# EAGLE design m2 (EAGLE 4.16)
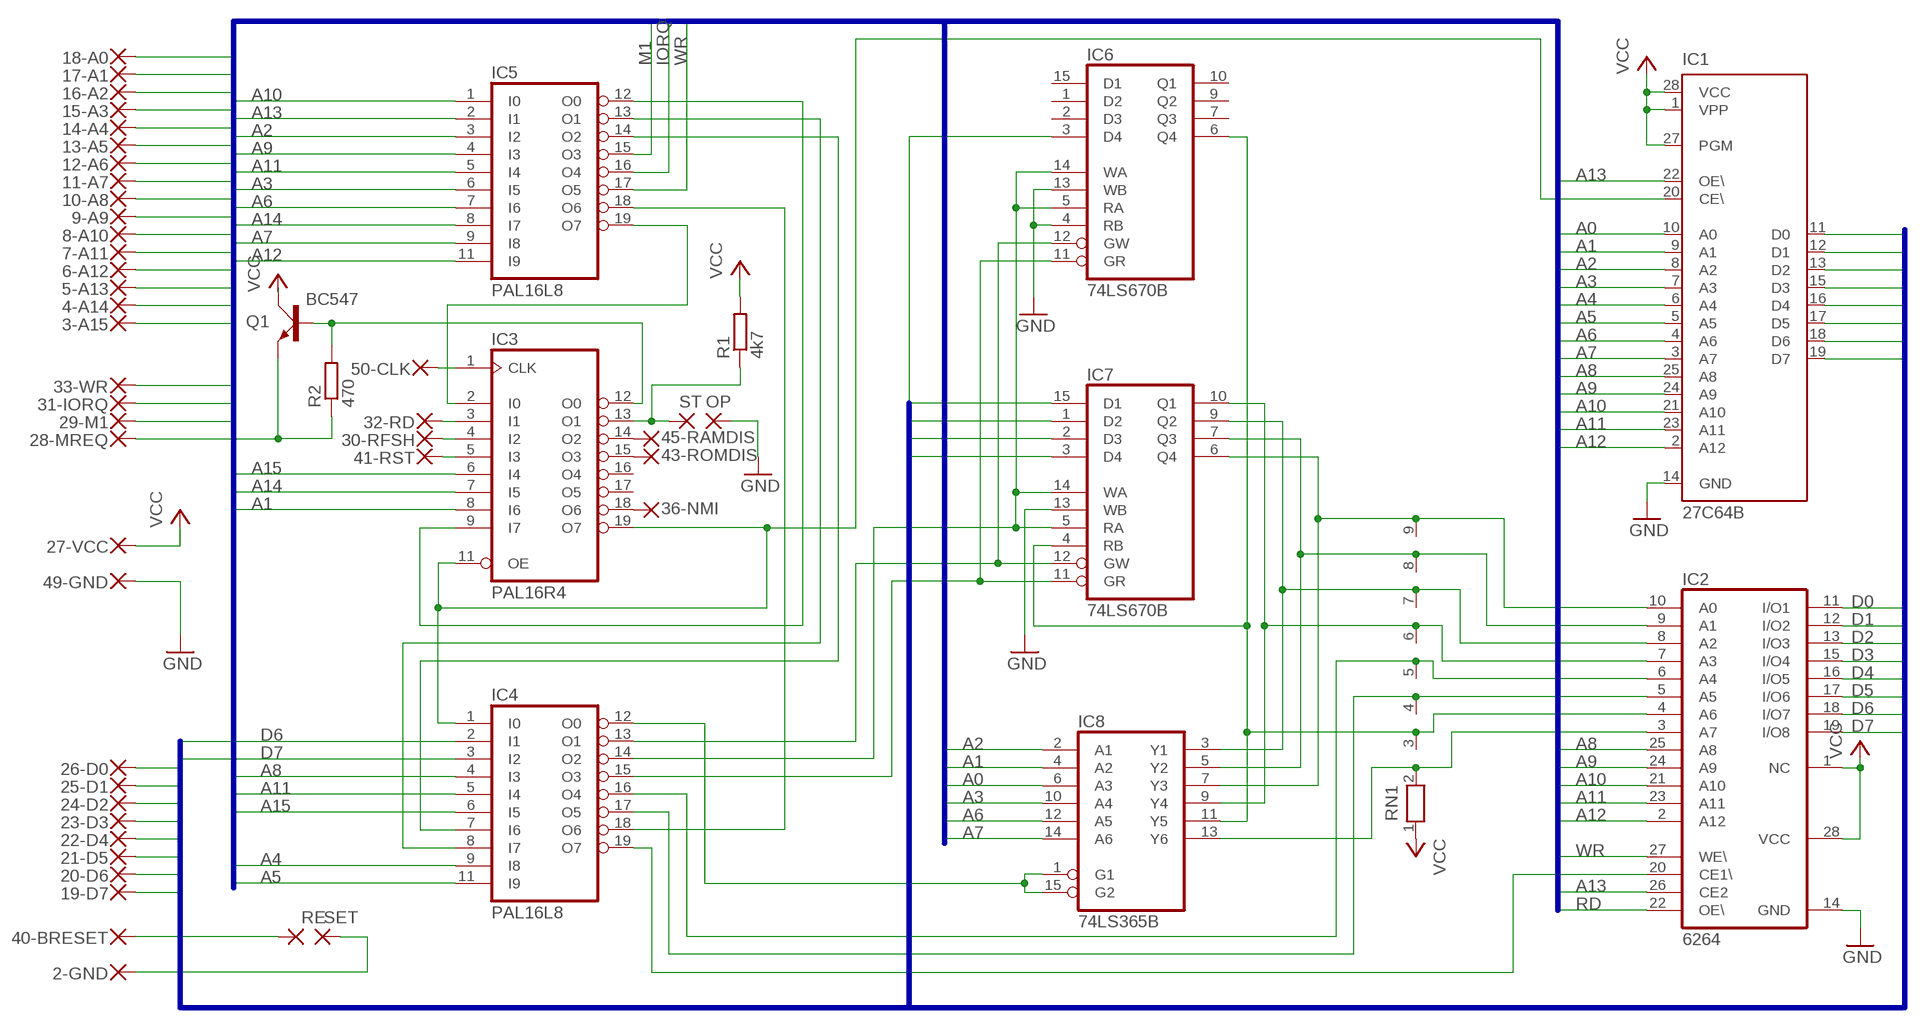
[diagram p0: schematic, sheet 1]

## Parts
2-GND  1,27-REDONDO0.8  [1,27/0,8-REDONDO]
3-A15  1,27-REDONDO0.8  [1,27/0,8-REDONDO]
4-A14  1,27-REDONDO0.8  [1,27/0,8-REDONDO]
5-A13  1,27-REDONDO0.8  [1,27/0,8-REDONDO]
6-A12  1,27-REDONDO0.8  [1,27/0,8-REDONDO]
7-A11  1,27-REDONDO0.8  [1,27/0,8-REDONDO]
8-A10  1,27-REDONDO0.8  [1,27/0,8-REDONDO]
9-A9  1,27-REDONDO0.8  [1,27/0,8-REDONDO]
10-A8  1,27-REDONDO0.8  [1,27/0,8-REDONDO]
11-A7  1,27-REDONDO0.8  [1,27/0,8-REDONDO]
12-A6  1,27-REDONDO0.8  [1,27/0,8-REDONDO]
13-A5  1,27-REDONDO0.8  [1,27/0,8-REDONDO]
14-A4  1,27-REDONDO0.8  [1,27/0,8-REDONDO]
15-A3  1,27-REDONDO0.8  [1,27/0,8-REDONDO]
16-A2  1,27-REDONDO0.8  [1,27/0,8-REDONDO]
17-A1  1,27-REDONDO0.8  [1,27/0,8-REDONDO]
18-A0  1,27-REDONDO0.8  [1,27/0,8-REDONDO]
19-D7  1,27-REDONDO0.8  [1,27/0,8-REDONDO]
20-D6  1,27-REDONDO0.8  [1,27/0,8-REDONDO]
21-D5  1,27-REDONDO0.8  [1,27/0,8-REDONDO]
22-D4  1,27-REDONDO0.8  [1,27/0,8-REDONDO]
23-D3  1,27-REDONDO0.8  [1,27/0,8-REDONDO]
24-D2  1,27-REDONDO0.8  [1,27/0,8-REDONDO]
25-D1  1,27-REDONDO0.8  [1,27/0,8-REDONDO]
26-D0  1,27-REDONDO0.8  [1,27/0,8-REDONDO]
27-VCC  1,27-REDONDO0.8  [1,27/0,8-REDONDO]
28-MREQ  1,27-REDONDO0.8  [1,27/0,8-REDONDO]
29-M1  1,27-REDONDO0.8  [1,27/0,8-REDONDO]
30-RFSH  1,27-REDONDO0.8  [1,27/0,8-REDONDO]
31-IORQ  1,27-REDONDO0.8  [1,27/0,8-REDONDO]
32-RD  1,27-REDONDO0.8  [1,27/0,8-REDONDO]
33-WR  1,27-REDONDO0.8  [1,27/0,8-REDONDO]
36-NMI  1,27-REDONDO0.8  [1,27/0,8-REDONDO]
40-BRESET  1,27-REDONDO0.8  [1,27/0,8-REDONDO]
41-RST  1,27-REDONDO0.8  [1,27/0,8-REDONDO]
43-ROMDIS  1,27-REDONDO0.8  [1,27/0,8-REDONDO]
45-RAMDIS  1,27-REDONDO0.8  [1,27/0,8-REDONDO]
49-GND  1,27-REDONDO0.8  [1,27/0,8-REDONDO]
50-CLK  1,27-REDONDO0.8  [1,27/0,8-REDONDO]
IC1  27C64B  [DIL28-6B]
IC2  6264  4364CB  [DIL28-6B]
IC3  PAL16R4  16R4B  [DIL20B]
IC4  PAL16L8  16L8B  [DIL20B]
IC5  PAL16L8  16L8B  [DIL20B]
IC6  74LS670B  [DIL16-B]
IC7  74LS670B  [DIL16-B]
IC8  74LS365B  [DIL16-B]
OP  2,54/1,1  [2,54/1,1]
Q1  BC547  [SOT54A]
R1  4k7  R-EU_0207/5V  [0207/5V]
R2  470  R-EU_0207/10  [0207/10]
RE  2,54/1,1  [2,54/1,1]
RN1  RN08  [RN-9]
SET  2,54/1,1  [2,54/1,1]
ST  2,54/1,1  [2,54/1,1]

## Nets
A0: 18-A0.1(P) IC1.10(A0) IC8.6(A3)
A1: 17-A1.1(P) IC1.9(A1) IC3.8(I6) IC8.4(A2)
A2: 16-A2.1(P) IC1.8(A2) IC5.3(I2) IC8.2(A1)
A3: 15-A3.1(P) IC1.7(A3) IC5.6(I5) IC8.10(A4)
A4: 14-A4.1(P) IC1.6(A4) IC4.9(I8)
A5: 13-A5.1(P) IC1.5(A5) IC4.11(I9)
A6: 12-A6.1(P) IC1.4(A6) IC5.7(I6) IC8.12(A5)
A7: 11-A7.1(P) IC1.3(A7) IC5.9(I8) IC8.14(A6)
A8: 10-A8.1(P) IC1.25(A8) IC2.25(A8) IC4.4(I3)
A9: 9-A9.1(P) IC1.24(A9) IC2.24(A9) IC5.4(I3)
A10: 8-A10.1(P) IC1.21(A10) IC2.21(A10) IC5.1(I0)
A11: 7-A11.1(P) IC1.23(A11) IC2.23(A11) IC4.5(I4) IC5.5(I4)
A12: 6-A12.1(P) IC1.2(A12) IC2.2(A12) IC5.11(I9)
A13: 5-A13.1(P) IC1.22(OE\) IC2.26(CE2) IC5.2(I1)
A14: 4-A14.1(P) IC3.7(I5) IC5.8(I7)
A15: 3-A15.1(P) IC3.6(I4) IC4.6(I5)
BRESET: 40-BRESET.1(P) RE.1(P)
CLK: 50-CLK.1(P) IC3.1(CLK)
D0: 26-D0.1(P) IC1.11(D0) IC2.11(I/O1) IC7.3(D4)
D1: 25-D1.1(P) IC1.12(D1) IC2.12(I/O2) IC7.2(D3)
D2: 24-D2.1(P) IC1.13(D2) IC2.13(I/O3) IC7.1(D2)
D3: 23-D3.1(P) IC1.15(D3) IC2.15(I/O4) IC7.15(D1)
D4: 22-D4.1(P) IC1.16(D4) IC2.16(I/O5) IC6.3(D4)
D5: 21-D5.1(P) IC1.17(D5) IC2.17(I/O6)
D6: 20-D6.1(P) IC1.18(D6) IC2.18(I/O7) IC4.2(I1)
D7: 19-D7.1(P) IC1.19(D7) IC2.19(I/O8) IC4.3(I2)
GND: 49-GND.1(P) IC1.14(GND) IC2.14(GND) IC6.4(RB) IC6.13(WB) IC7.13(WB) OP.1(P)
IORQ: 31-IORQ.1(P) IC5.16(O4)
M1: 29-M1.1(P) IC5.15(O3)
MREQ: 28-MREQ.1(P) Q1.E R2.1
N$2: 41-RST.1(P) IC3.5(I3)
N$4: IC3.13(O1) R1.1 ST.1(P)
N$5: IC1.20(CE\) IC3.11(OE) IC3.19(O7) IC4.1(I0)
N$8: IC3.9(I7) IC5.12(O0)
N$9: 45-RAMDIS.1(P) IC3.14(O2)
N$10: IC4.8(I7) IC5.13(O1)
N$11: IC4.7(I6) IC5.14(O2)
N$12: IC4.18(O6) IC5.18(O6)
N$13: IC3.2(I0) IC5.19(O7)
N$14: 43-ROMDIS.1(P) IC3.15(O3)
N$22: 2-GND.1(P) SET.1(P)
N$27: IC2.4(A6) IC6.6(Q4) IC7.4(RB) IC8.11(Y5) RN1.3
N$28: IC2.7(A3) IC7.10(Q1) IC8.9(Y4) RN1.6
N$29: IC2.8(A2) IC7.9(Q2) IC8.3(Y1) RN1.7
N$30: IC2.9(A1) IC7.7(Q3) IC8.5(Y2) RN1.8
N$31: IC2.10(A0) IC7.6(Q4) IC8.7(Y3) RN1.9
N$32: IC2.6(A4) IC4.16(O4) RN1.5
N$33: IC2.5(A5) IC4.17(O5) RN1.4
N$34: IC2.3(A7) IC8.13(Y6) RN1.2
N$35: IC4.12(O0) IC8.1(G1) IC8.15(G2)
N$37: IC3.12(O0) Q1.B R2.2
N$38: IC4.14(O2) IC6.5(RA) IC6.14(WA) IC7.5(RA) IC7.14(WA)
N$39: IC4.15(O3) IC6.11(GR) IC7.11(GR)
N$40: IC4.13(O1) IC6.12(GW) IC7.12(GW)
N$42: IC2.20(CE1\) IC4.19(O7)
NMI: 36-NMI.1(P) IC3.18(O6)
RD: 32-RD.1(P) IC2.22(OE\) IC3.3(I1)
RFSH: 30-RFSH.1(P) IC3.4(I2)
VCC: 27-VCC.1(P) IC1.1(VPP) IC1.27(PGM) IC1.28(VCC) IC2.1(NC) IC2.28(VCC) Q1.C R1.2 RN1.1
WR: 33-WR.1(P) IC2.27(WE\) IC5.17(O5)
Unconnected: IC1.26(NC) IC3.16(O4) IC3.17(O5) IC6.1(D2) IC6.2(D3) IC6.7(Q3) IC6.9(Q2) IC6.10(Q1) IC6.15(D1)

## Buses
A[0..15],RD,WR,IORQ,M1
D[0..7]

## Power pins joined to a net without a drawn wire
GND: IC3.10(GND) IC4.10(GND) IC5.10(GND) IC6.8(GND) IC7.8(GND) IC8.8(GND)
VCC: IC3.20(VCC) IC4.20(VCC) IC5.20(VCC) IC6.16(VCC) IC7.16(VCC) IC8.16(VCC)

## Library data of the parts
2-GND 3-A15 4-A14 5-A13 6-A12 7-A11 8-A10 9-A9 10-A8 11-A7 12-A6 13-A5 14-A4 15-A3 16-A2 17-A1 18-A0 19-D7 20-D6 21-D5 22-D4 23-D3 24-D2 25-D1 26-D0 27-VCC 28-MREQ 29-M1 30-RFSH 31-IORQ 32-RD 33-WR 36-NMI 40-BRESET 41-RST 43-ROMDIS 45-RAMDIS 49-GND 50-CLK = wirepad2:1,27-REDONDO
IC1 = microchip:27*64: CMOS EPROM 64 K (8 K x 8), low voltage
IC2 = memory-nec:4364C: MEMORY
IC3 = pal:16R4: PAL
IC4 IC5 = pal:16L8: PAL
IC6 IC7 = 74xx-eu2:74*670: 4 by 4 REGISTER FILES, 3-state
IC8 = 74xx-eu2:74*365: Hex BUS DRIVER, 3-state
OP RE SET ST = wirepad:2,54/1,1: THROUGH-HOLE PAD
Q1 = transistor-small-signal:BC547: NPN TRANSISTOR
R1 R2 = rcl:R-EU_: RESISTOR, European symbol
RN1 = discrete2:RN08

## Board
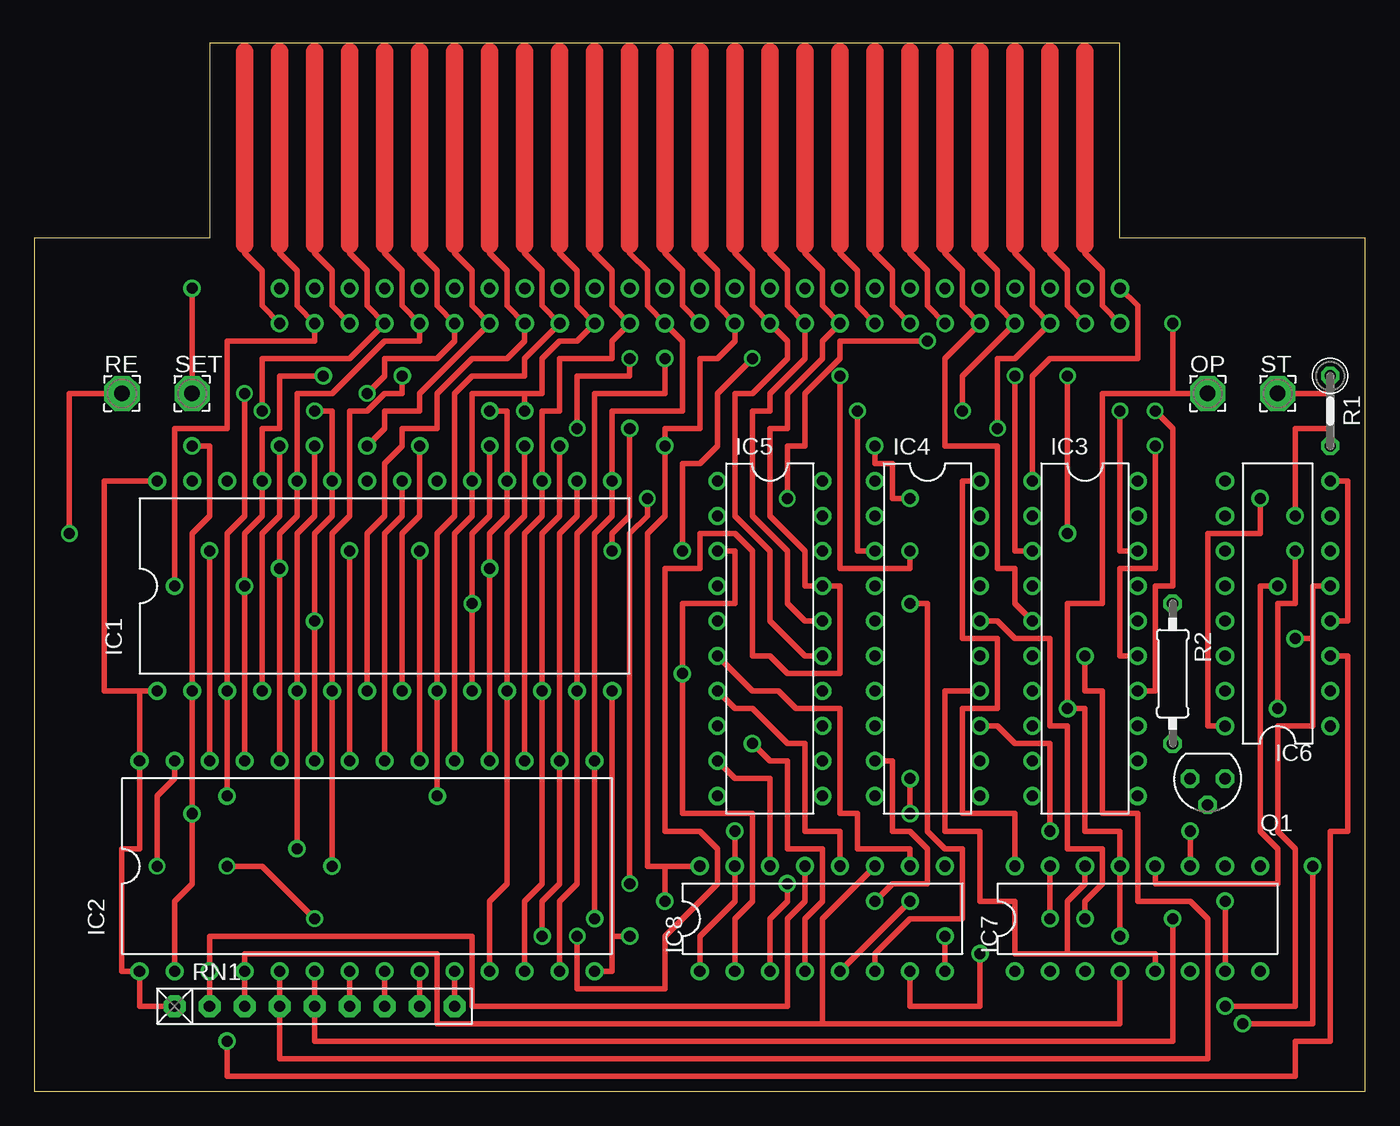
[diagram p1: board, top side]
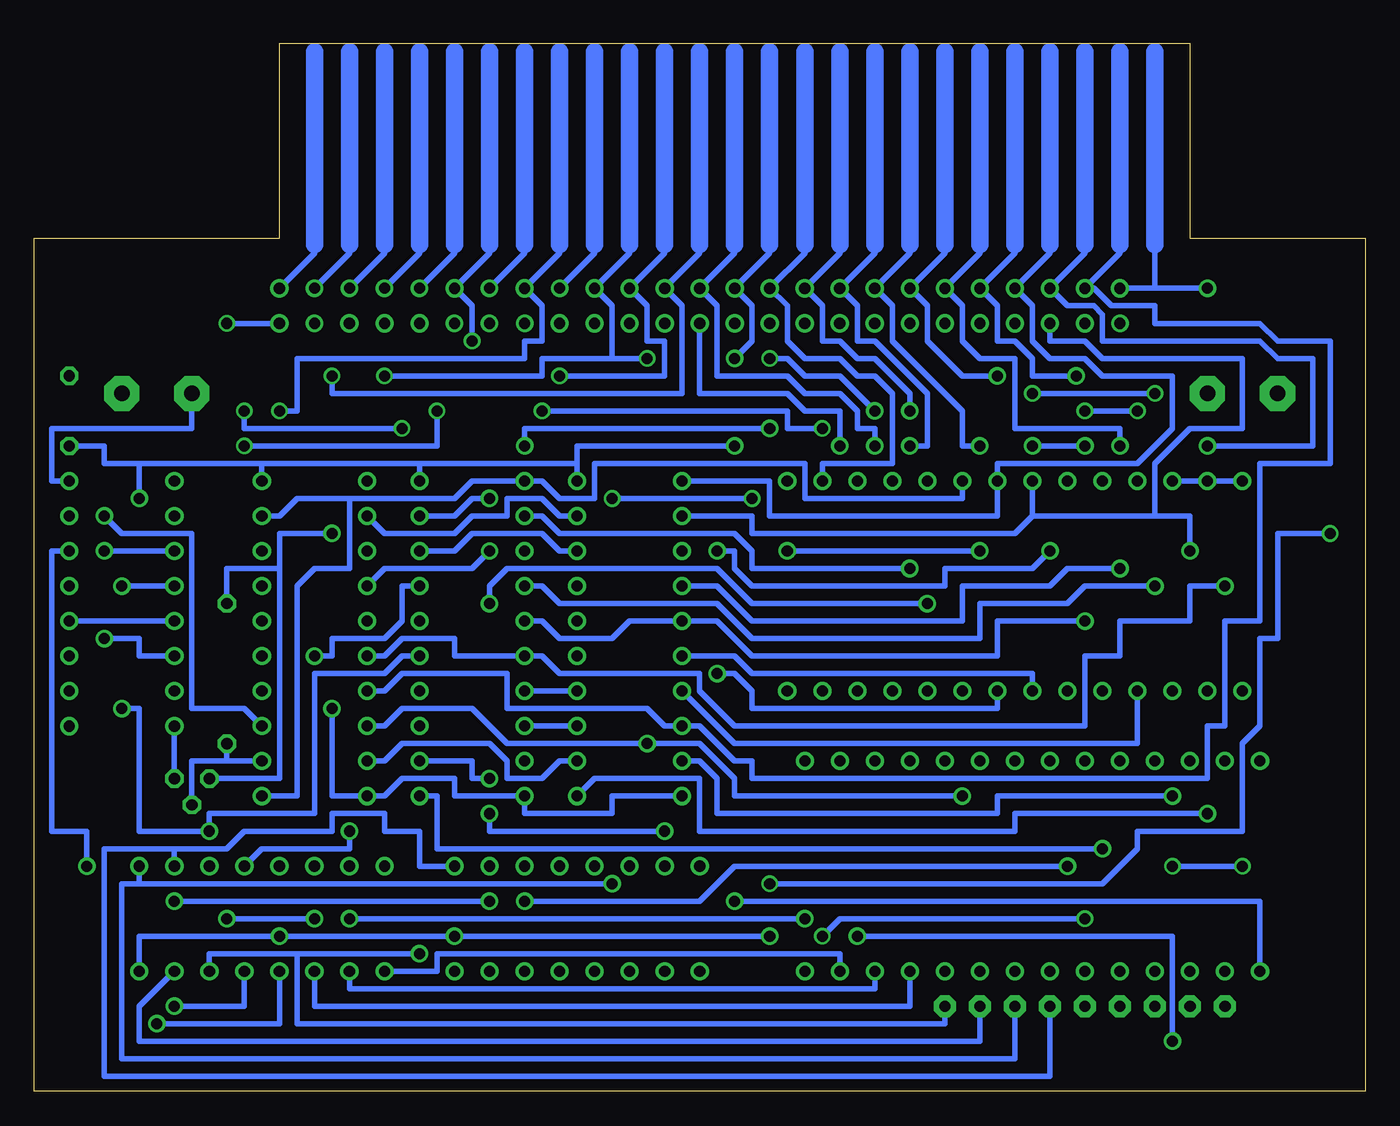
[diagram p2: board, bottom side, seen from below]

Size 96.5 x 76.03 mm. Coordinates in mm from the lower left corner, seen from the top.
Outline: 0,0 96.5,0 96.5,61.9 78.73,61.9 78.73,76.03 12.69,76.03 12.69,61.9 0,61.9 0,0
Copper layers (1*16): Top 0.035mm / dielectric 1.5mm / Bottom 0.035mm
Design rules "default": minimum track width 10mil, minimum drill 24mil, track to track 8mil, track to pad 8mil, pad to pad 8mil, via to via 8mil, smd to smd 8mil, copper to edge 40mil, drill to drill 8mil, minimum pad ring 10mil, minimum via ring 8mil, stop-mask expansion 4mil, vias tented up to drill 0mil, thermal gap 10mil

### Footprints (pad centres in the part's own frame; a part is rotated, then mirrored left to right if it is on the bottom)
1,27/0,8-REDONDO = drill 0.813 pad 1.27 round: 1 0,0
DIL28-6B = drill 0.8 round: 1 -16.51,-7.62; 2 -13.97,-7.62; 3 -11.43,-7.62; 4 -8.89,-7.62; 5 -6.35,-7.62; 6 -3.81,-7.62; 7 -1.27,-7.62; 8 1.27,-7.62; 9 3.81,-7.62; 10 6.35,-7.62; 11 8.89,-7.62; 12 11.43,-7.62; 13 13.97,-7.62; 14 16.51,-7.62; 15 16.51,7.62; 16 13.97,7.62; 17 11.43,7.62; 18 8.89,7.62; 19 6.35,7.62; 20 3.81,7.62; 21 1.27,7.62; 22 -1.27,7.62; 23 -3.81,7.62; 24 -6.35,7.62; 25 -8.89,7.62; 26 -11.43,7.62; 27 -13.97,7.62; 28 -16.51,7.62
DIL20B = drill 0.8 round: 1 -11.43,-3.81; 2 -8.89,-3.81; 3 -6.35,-3.81; 4 -3.81,-3.81; 5 -1.27,-3.81; 6 1.27,-3.81; 7 3.81,-3.81; 8 6.35,-3.81; 9 8.89,-3.81; 10 11.43,-3.81; 11 11.43,3.81; 12 8.89,3.81; 13 6.35,3.81; 14 3.81,3.81; 15 1.27,3.81; 16 -1.27,3.81; 17 -3.81,3.81; 18 -6.35,3.81; 19 -8.89,3.81; 20 -11.43,3.81
DIL16-B = drill 0.813 round: 1 -8.89,-3.81; 2 -6.35,-3.81; 3 -3.81,-3.81; 4 -1.27,-3.81; 5 1.27,-3.81; 6 3.81,-3.81; 7 6.35,-3.81; 8 8.89,-3.81; 9 8.89,3.81; 10 6.35,3.81; 11 3.81,3.81; 12 1.27,3.81; 13 -1.27,3.81; 14 -3.81,3.81; 15 -6.35,3.81; 16 -8.89,3.81
2,54/1,1 = drill 1.118 pad 2.54 octagon: 1 0,0
SOT54A = drill 0.813 octagon: B 0,1.905; C -1.27,0; E 1.27,0
0207/5V = drill 0.813 octagon: 1 -2.54,0; 2 2.54,0
0207/10 = drill 0.813 octagon: 1 -5.08,0; 2 5.08,0
RN-9 = drill 0.813 pad 1.6 octagon: 1 -10.16,0; 2 -7.62,0; 3 -5.08,0; 4 -2.54,0; 5 0,0; 6 2.54,0; 7 5.08,0; 8 7.62,0; 9 10.16,0

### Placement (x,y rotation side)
2-GND  17.78,58.26 0 top
3-A15  20.32,55.72 180 top
4-A14  20.32,58.26 0 top
5-A13  22.86,55.72 180 top
6-A12  22.86,58.26 0 top
7-A11  25.39,55.72 180 top
8-A10  25.39,58.26 0 top
9-A9  27.94,55.72 180 top
10-A8  27.94,58.26 0 top
11-A7  30.48,55.72 180 top
12-A6  30.48,58.26 0 top
13-A5  33.02,55.72 180 top
14-A4  33.02,58.26 0 top
15-A3  35.55,55.72 180 top
16-A2  35.55,58.26 0 top
17-A1  38.09,55.72 180 top
18-A0  38.09,58.26 0 top
19-D7  40.63,55.72 180 top
20-D6  40.63,58.26 0 top
21-D5  43.17,55.72 180 top
22-D4  43.17,58.26 0 top
23-D3  45.71,55.72 180 top
24-D2  45.71,58.26 0 top
25-D1  48.25,55.72 180 top
26-D0  48.25,58.26 0 top
27-VCC  50.79,55.72 180 top
28-MREQ  50.79,58.26 0 top
29-M1  53.34,55.72 180 top
30-RFSH  53.34,58.26 0 top
31-IORQ  55.88,55.72 180 top
32-RD  55.88,58.26 0 top
33-WR  58.41,55.72 180 top
36-NMI  60.95,58.26 0 top
40-BRESET  66.04,58.26 0 top
41-RST  68.58,55.72 180 top
43-ROMDIS  71.12,55.72 180 top
45-RAMDIS  73.66,55.72 180 top
49-GND  78.73,55.72 180 top
50-CLK  78.73,58.26 0 top
IC1  25.39,36.66 0 top
IC2  24.12,16.35 0 top
IC3  76.2,32.86 270 top
IC4  64.77,32.86 270 top
IC5  53.34,32.86 270 top
IC6  90.17,35.4 90 top
IC7  80.01,12.54 0 top
IC8  57.14,12.54 0 top
OP  85.09,50.63 0 top
Q1  85.09,22.7 180 top
R1  93.98,49.37 270 top
R2  82.55,30.32 270 top
RE  6.34,50.63 0 top
RN1  20.32,6.18 0 top
SET  11.42,50.63 0 top
ST  90.17,50.63 0 top

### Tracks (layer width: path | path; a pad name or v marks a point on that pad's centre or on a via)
A0  (via drill 0.8 pad 1.27)
  Top 0.406: IC1.10 v31.75,35.4 31.75,40.48 33.02,41.74 v33.02,46.83 | IC8.6 60.95,10 63.49,12.54 67.31,12.54 67.31,17.62 66.04,17.62 64.77,18.89 64.77,35.4 v63.49,35.4
  Bottom 0.406: v31.75,35.4 44.45,35.4 46.98,37.94 62.22,37.94 63.49,36.66 v63.49,35.4 | v33.02,46.83 31.75,46.83 31.75,50.63 35.55,54.45 36.82,54.45 36.82,56.98 18-A0.1 35.55,60.8 35.55,61.43
  Bottom 1.27: 35.55,62.06 35.55,61.43 35.55,75.4
A1  (via drill 0.8 pad 1.27)
  Top 0.406: v29.21,21.43 IC1.9 29.21,40.48 30.48,41.74 30.48,50.63 31.75,51.91 35.55,51.91 35.55,53.18 17-A1.1 36.82,56.98 36.82,59.52 35.55,60.8 35.55,61.43 | IC8.4 55.88,12.54 57.14,13.81 57.14,17.62 54.6,17.62 54.6,23.96 53.34,23.96 v52.06,25.23
  Top 1.27: 35.55,62.06 35.55,61.43 35.55,75.4
  Bottom 0.406: v29.21,21.43 45.71,21.43 45.71,22.7 48.25,25.23 v52.06,25.23 62.22,25.23 64.77,27.78 69.84,27.78 71.12,26.51 IC3.8
A2  (via drill 0.8 pad 1.27)
  Top 0.406: IC8.2 50.79,12.54 52.06,13.81 52.06,20.16 46.98,20.16 v46.98,30.32 46.98,35.4 50.79,35.4 50.79,39.2 IC5.3 | IC1.8 26.67,40.48 27.94,41.74 v27.94,46.83
  Bottom 0.406: IC1.8 26.67,27.78 44.45,27.78 44.45,29.05 45.71,30.32 v46.98,30.32 | v27.94,46.83 29.21,46.83 29.21,49.37 34.28,54.45 34.28,56.98 16-A2.1 33.02,60.8 33.02,61.43
  Bottom 1.27: 33.02,62.06 33.02,61.43 33.02,75.4
A3
  Top 0.406: IC8.10 63.49,17.62 59.68,17.62 59.68,20.16 58.41,20.16 58.41,27.78 55.24,27.78 53.97,29.05 52.06,29.05 IC5.6 | IC1.7 24.12,40.48 25.39,41.74 25.39,45.55 26.67,46.83 26.67,48.09 29.21,48.09 29.21,50.63 31.75,53.18 34.28,53.18 35.55,54.45 15-A3.1 34.28,56.98 34.28,59.52 33.02,60.8 33.02,61.43
  Top 1.27: 33.02,62.06 33.02,61.43 33.02,75.4
  Bottom 0.406: IC1.7 24.12,30.32 44.45,30.32 45.71,31.59 IC5.6
A4  (via drill 0.8 pad 1.27)
  Top 0.406: IC4.9 62.22,23.96 62.22,18.89 63.49,18.89 64.77,17.62 64.77,15.08 62.22,15.08 v60.95,13.81 | v21.59,16.35 IC1.6 21.59,40.48 22.86,41.74 22.86,49.37 24.12,49.37 25.39,50.63 26.67,50.63 v26.67,51.91
  Bottom 0.406: v60.95,13.81 48.25,13.81 45.71,16.35 v21.59,16.35 | v26.67,51.91 29.21,51.91 31.75,54.45 31.75,56.98 14-A4.1 30.48,60.8 30.48,61.43
  Bottom 1.27: 30.48,61.43 30.48,75.4
A5  (via drill 0.8 pad 1.27)
  Top 0.406: v19.05,17.62 IC1.5 19.05,40.48 20.32,41.74 v20.32,46.83 | v24.12,46.83 25.39,48.09 25.39,49.37 27.94,49.37 27.94,50.63 13-A5.1 31.75,56.98 31.75,59.52 30.48,60.8 30.48,61.43
  Top 1.27: 30.48,62.06 30.48,61.43 30.48,75.4
  Bottom 0.406: IC4.11 67.31,21.43 67.31,17.62 v19.05,17.62 | v20.32,46.83 v24.12,46.83
A6  (via drill 0.8 pad 1.27)
  Top 0.406: IC1.4 16.51,40.48 17.78,41.74 v17.78,46.83 | IC8.12 58.41,18.89 55.88,18.89 55.88,25.23 54.6,25.23 52.06,27.78 50.79,27.78 IC5.7
  Bottom 0.406: IC1.4 16.51,25.23 45.71,25.23 IC5.7 | v17.78,46.83 17.78,48.09 25.39,48.09 25.39,53.18 27.94,53.18 29.21,54.45 29.21,56.98 12-A6.1 27.94,60.8 27.94,61.43
  Bottom 1.27: 27.94,61.43 27.94,75.4
A7  (via drill 0.8, 0.8 pad 1.27)
  Top 0.406: v13.96,21.43 IC1.3 13.96,40.48 15.23,41.74 v15.23,50.63 | IC8.14 53.34,22.7 50.79,22.7 IC5.9 | v24.12,50.63 25.39,51.91 25.39,53.18 29.21,53.18 30.48,54.45 11-A7.1 29.21,56.98 29.21,59.52 27.94,60.8 27.94,61.43
  Top 1.27: 27.94,62.06 27.94,61.43 27.94,75.4
  Bottom 0.406: IC5.9 48.25,23.96 46.98,22.7 46.98,20.16 26.67,20.16 26.67,21.43 v13.96,21.43 | v15.23,50.63 v24.12,50.63
A8  (via drill 0.8 pad 1.27)
  Top 0.406: IC2.25 v15.23,36.66 15.23,40.48 16.51,41.74 IC1.25 16.51,48.09 17.78,48.09 17.78,51.91 v20.95,51.91
  Bottom 0.406: IC4.4 59.68,36.66 58.41,35.4 46.98,35.4 44.45,32.86 27.94,32.86 27.94,35.4 21.59,35.4 20.32,36.66 v15.23,36.66 | v20.95,51.91 24.12,51.91 24.12,53.18 25.39,54.45 26.67,54.45 26.67,56.98 10-A8.1 25.39,60.8 25.39,61.43
  Bottom 1.27: 25.39,61.43 25.39,75.4
A9  (via drill 0.8 pad 1.27)
  Top 0.406: IC2.24 v17.78,37.94 17.78,40.48 19.05,41.74 IC1.24 19.05,50.63 21.59,50.63 25.39,54.45 27.94,54.45 9-A9.1 26.67,56.98 26.67,59.52 25.39,60.8 25.39,61.43
  Top 1.27: 25.39,62.06 25.39,61.43 25.39,75.4
  Bottom 0.406: IC5.4 46.98,36.66 44.45,34.12 29.21,34.12 29.21,36.66 22.86,36.66 21.59,37.94 v17.78,37.94
A10
  Top 0.406: IC2.21 25.39,40.48 26.67,41.74 IC1.21
  Bottom 0.406: IC5.1 43.17,44.29 43.17,41.74 26.67,41.74 IC1.21 26.67,45.55 16.51,45.55 13.96,48.09 13.96,51.91 19.05,51.91 20.32,53.18 22.86,53.18 24.12,54.45 24.12,56.98 8-A10.1 22.86,60.8 22.86,61.43
  Bottom 1.27: 22.86,61.43 22.86,75.4
A11  (via drill 0.8, 0.8 pad 1.27)
  Top 0.406: IC2.23 v20.32,34.12 20.32,40.48 21.59,41.74 IC1.23 21.59,49.37 v20.32,49.37 | v16.51,49.37 16.51,53.18 22.86,53.18 7-A11.1 24.12,56.98 24.12,59.52 22.86,60.8 22.86,61.43
  Top 1.27: 22.86,62.06 22.86,61.43 22.86,75.4
  Bottom 0.406: IC4.5 59.68,34.12 58.41,32.86 54.6,32.86 53.34,34.12 IC5.5 46.98,34.12 44.45,31.59 26.67,31.59 26.67,34.12 v20.32,34.12 | v20.32,49.37 v16.51,49.37
A12  (via drill 0.8 pad 1.27)
  Top 0.406: IC2.2 10.15,13.81 11.42,15.08 v11.42,20.16 IC1.2 11.42,40.48 12.69,41.74 12.69,46.83 v11.42,46.83
  Bottom 0.406: IC5.11 55.88,22.7 48.25,22.7 48.25,18.89 25.39,18.89 25.39,20.16 v11.42,20.16 | v11.42,46.83 3.81,46.83 3.81,53.18 6.34,53.18 7.62,54.45 19.05,54.45 19.05,56.35 19.68,56.98 21.59,56.98 6-A12.1 20.32,60.8 20.32,61.43
  Bottom 1.27: 20.32,61.43 20.32,75.4
A13  (via drill 0.8 pad 1.27)
  Top 0.406: IC2.26 v12.69,39.2 | 5-A13.1 21.59,56.98 21.59,59.52 20.32,60.8 20.32,61.43
  Top 1.27: 20.32,62.06 20.32,61.43 20.32,75.4
  Bottom 0.406: IC5.2 44.45,41.74 44.45,40.48 25.39,40.48 24.12,41.74 | 24.12,41.74 IC1.22 | v12.69,39.2 12.69,41.74 15.23,41.74 | 15.23,41.74 24.12,41.74 | 15.23,41.74 15.23,45.55 12.69,48.09 8.88,48.09 8.88,53.18 19.05,53.18 20.32,54.45 22.86,54.45 5-A13.1
A14
  Bottom 0.406: IC3.7 71.12,29.05 69.84,30.32 62.22,30.32 62.22,27.78 52.06,27.78 50.79,26.51 IC5.8 48.25,26.51 45.71,23.96 44.45,23.96 44.45,22.7 11.42,22.7 11.42,26.51 10.15,26.51 10.15,34.12 7.62,34.12 7.62,45.55 2.54,45.55 2.54,54.45 6.34,54.45 7.62,55.72 15.23,55.72 15.23,56.98 18.41,56.98 19.68,58.26 4-A14.1 17.78,60.8 17.78,61.43
  Bottom 1.27: 17.78,61.43 17.78,75.4
A15  (via drill 0.8 pad 1.27)
  Top 0.406: v10.15,36.66 10.15,48.09 13.96,48.09 13.96,54.45 20.32,54.45 3-A15.1 19.05,56.98 19.05,59.52 17.78,60.8 17.78,61.43
  Top 1.27: 17.78,62.06 17.78,61.43 17.78,75.4
  Bottom 0.406: IC3.6 71.12,31.59 69.84,32.86 66.04,32.86 66.04,31.59 IC4.6 59.68,31.59 58.41,30.32 48.25,30.32 48.25,29.05 45.71,26.51 20.32,26.51 20.32,31.59 17.78,31.59 17.78,34.12 12.69,34.12 12.69,36.66 v10.15,36.66
BRESET  (via drill 0.8)
  Top 0.406: v64.77,54.45 58.41,54.45 58.41,53.18 55.88,50.63 55.88,46.83 54.6,46.83 v54.6,43.02 | v44.45,43.02 44.45,41.74 43.17,40.48 v43.17,15.08 | v2.54,40.48 2.54,50.63 RE.1
  Bottom 0.406: v64.77,54.45 64.77,56.98 40-BRESET.1 63.49,60.8 63.49,61.43 | v44.45,43.02 v54.6,43.02 | v43.17,15.08 19.05,15.08 16.51,17.62 16.51,18.89 8.88,18.89 8.88,25.23 7.62,26.51 7.62,32.86 6.34,32.86 6.34,40.48 v2.54,40.48
  Bottom 1.27: 63.49,62.06 63.49,61.43 63.49,75.4
CLK
  Top 0.406: IC3.1 72.39,51.91 73.66,53.18 80.01,53.18 80.01,56.98 50-CLK.1
  Bottom 0.406: 50-CLK.1 76.2,60.8 76.2,61.43
  Bottom 1.27: 76.2,62.06 76.2,61.43 76.2,75.4
D0  (via drill 0.8 pad 1.27)
  Top 0.406: IC2.11 33.02,13.81 34.28,15.08 IC1.11 34.28,40.48 35.55,41.74 v35.55,46.83
  Bottom 0.406: IC2.11 33.02,6.18 76.2,6.18 IC7.3 | v35.55,46.83 35.55,48.09 36.82,48.09 36.82,49.37 38.09,50.63 40.63,50.63 41.9,51.91 46.98,51.91 46.98,56.98 26-D0.1 45.71,60.8 45.71,61.43
  Bottom 1.27: 45.71,62.06 45.71,61.43 45.71,75.4
D1  (via drill 0.8 pad 1.27)
  Top 0.406: IC2.12 35.55,13.81 36.82,15.08 IC1.12 36.82,40.48 38.09,41.74 v38.09,46.83 | 25-D1.1 46.98,56.98 46.98,59.52 45.71,60.8 45.71,61.43
  Top 1.27: 45.71,62.06 45.71,61.43 45.71,75.4
  Bottom 0.406: IC2.12 35.55,7.46 73.66,7.46 IC7.2 | v38.09,46.83 38.09,49.37 40.63,49.37 41.9,50.63 48.25,50.63 25-D1.1
D2  (via drill 0.8 pad 1.27)
  Top 0.406: IC2.13 38.09,13.81 39.36,15.08 IC1.13 39.36,40.48 40.63,41.74 40.63,50.63 45.71,50.63 v45.71,53.18
  Bottom 0.406: IC2.13 38.09,10 67.31,10 67.31,8.73 IC7.1 | v45.71,53.18 44.45,54.45 44.45,56.98 24-D2.1 43.17,60.8 43.17,61.43
  Bottom 1.27: 43.17,62.06 43.17,61.43 43.17,75.4
D3  (via drill 0.8 pad 1.27)
  Top 0.406: v73.66,12.54 IC7.15 | v40.63,12.54 IC2.15 40.63,40.48 41.9,41.74 IC1.15 41.9,49.37 46.98,49.37 46.98,54.45 23-D3.1 44.45,56.98 44.45,59.52 43.17,60.8 43.17,61.43
  Top 1.27: 43.17,62.06 43.17,61.43 43.17,75.4
  Bottom 0.406: v40.63,12.54 v73.66,12.54
D4  (via drill 0.8 pad 1.27)
  Top 0.406: IC1.16 39.36,41.74 38.09,40.48 IC2.16 38.09,15.08 36.82,13.81 v36.82,11.27 | IC6.3 95.25,31.59 95.25,18.89 93.98,18.89 93.98,3.65 91.44,3.65 91.44,1.1 13.96,1.1 v13.96,3.65
  Bottom 0.406: IC1.16 39.36,45.55 34.28,45.55 34.28,50.63 35.55,51.91 36.82,51.91 38.09,53.18 40.63,53.18 41.9,54.45 41.9,56.98 22-D4.1 40.63,60.8 40.63,61.43 | v13.96,3.65 13.96,11.27 v36.82,11.27
  Bottom 1.27: 40.63,62.06 40.63,61.43 40.63,75.4
D5
  Top 0.406: IC2.17 35.55,40.48 36.82,41.74 IC1.17 36.82,49.37 38.09,49.37 38.09,53.18 41.9,53.18 41.9,54.45 21-D5.1 41.9,56.98 41.9,59.52 40.63,60.8 40.63,61.43
  Top 1.27: 40.63,62.06 40.63,61.43 40.63,75.4
D6  (via drill 0.8 pad 1.27)
  Top 0.406: IC2.18 v33.02,37.94 33.02,40.48 34.28,41.74 IC1.18 34.28,49.37 v33.02,49.37
  Bottom 0.406: IC4.2 59.68,41.74 58.41,40.48 45.71,40.48 44.45,39.2 44.45,37.94 v33.02,37.94 | v33.02,49.37 33.02,50.63 35.55,53.18 36.82,53.18 38.09,54.45 39.36,54.45 39.36,56.98 20-D6.1 38.09,60.8 38.09,61.43
  Bottom 1.27: 38.09,62.06 38.09,61.43 38.09,75.4
D7  (via drill 0.8, 0.8 pad 1.27)
  Top 0.406: IC2.19 30.48,40.48 31.75,41.74 IC1.19 31.75,50.63 35.55,50.63 | IC4.3 59.68,39.2 v59.68,49.37 | 35.55,50.63 v35.55,49.37 | 35.55,50.63 36.82,50.63 36.82,53.18 38.09,54.45 39.36,54.45 19-D7.1 39.36,56.98 39.36,59.52 38.09,60.8 38.09,61.43 | v39.36,48.09 39.36,51.91 43.17,51.91 v43.17,53.18
  Top 1.27: 38.09,62.06 38.09,61.43 38.09,75.4
  Bottom 0.406: v59.68,49.37 41.9,49.37 41.9,48.09 v39.36,48.09 | v43.17,53.18 41.9,53.18 40.63,51.91 38.09,51.91 v35.55,49.37
GND  (via drill 0.8, 0.8 pad 1.27)
  Top 0.406: v78.73,11.27 IC7.13 78.73,18.89 76.2,18.89 76.2,27.78 v74.93,27.78 74.93,35.4 77.47,35.4 77.47,50.63 82.55,50.63 | v66.04,11.27 IC8.8 | 41.9,11.27 v43.17,11.27 | 41.9,11.27 41.9,8.73 IC2.14 | 41.9,11.27 IC1.14 | IC6.8 95.25,44.29 95.25,34.12 IC6.4 | 82.55,50.63 v82.55,55.72 | 82.55,50.63 OP.1 | 49-GND.1 77.47,56.98 77.47,59.52 76.2,60.8 76.2,61.43
  Top 1.27: 76.2,62.06 76.2,61.43 76.2,75.4
  Bottom 0.406: IC7.8 88.9,11.27 v78.73,11.27 v66.04,11.27 v43.17,11.27 | IC6.4 IC6.13 | IC5.10 54.6,21.43 54.6,20.16 60.95,20.16 IC4.10 66.04,21.43 66.04,22.7 69.84,22.7 71.12,21.43 IC3.10 74.93,21.43 v74.93,27.78 | v82.55,55.72 49-GND.1 | IC6.8 95.25,44.29 95.25,48.09 85.09,48.09 OP.1
IORQ
  Top 0.406: IC5.16 55.88,34.12 54.6,35.4 54.6,39.2 52.06,41.74 52.06,49.37 53.34,49.37 53.34,50.63 55.88,53.18 31-IORQ.1 54.6,56.98 54.6,59.52 53.34,60.8 53.34,61.43
  Top 1.27: 53.34,62.06 53.34,61.43 53.34,75.4
M1
  Top 0.406: IC5.15 55.88,31.59 53.34,34.12 53.34,39.2 50.79,41.74 50.79,50.63 52.06,50.63 54.6,53.18 54.6,54.45 29-M1.1 52.06,56.98 52.06,59.52 50.79,60.8 50.79,61.43
  Top 1.27: 50.79,62.06 50.79,61.43 50.79,75.4
MREQ  (via drill 0.8, 0.8 pad 1.27)
  Top 0.406: v74.93,51.91 v74.93,40.48
  Bottom 0.406: Q1.E 78.73,22.7 78.73,37.94 | 78.73,37.94 82.55,37.94 R2.1 | 78.73,37.94 78.73,40.48 v74.93,40.48 | v74.93,51.91 74.93,50.63 49.52,50.63 49.52,56.98 28-MREQ.1 48.25,60.8 48.25,61.43
  Bottom 1.27: 48.25,62.06 48.25,61.43 48.25,75.4
N$1  (via drill 0.8 pad 1.27)
  Top 0.406: v17.78,55.72 16.51,56.98 16.51,59.52 15.23,60.8 15.23,61.43
  Top 1.27: 15.23,62.06 15.23,61.43 15.23,75.4
N$2
  Top 0.406: IC3.5 71.12,35.4 71.12,37.94 69.84,37.94 69.84,46.83 66.04,46.83 66.04,53.18 41-RST.1 67.31,56.98 67.31,59.52 66.04,60.8 66.04,61.43
  Top 1.27: 66.04,62.06 66.04,61.43 66.04,75.4
N$3  (via drill 0.8 pad 1.27)
  Bottom 0.406: v58.41,58.26 55.88,60.8 55.88,61.43
  Bottom 1.27: 55.88,62.06 55.88,61.43 55.88,75.4
N$4  (via drill 0.8 pad 1.27)
  Top 0.406: 93.98,50.63 ST.1 | 93.98,50.63 R1.1 | 93.98,50.63 93.98,48.09 91.44,48.09 v91.44,41.74
  Bottom 0.406: IC3.13 81.28,27.78 85.09,27.78 85.09,40.48 90.17,40.48 v91.44,41.74
N$5
  Bottom 0.406: IC1.20 29.21,43.02 40.63,43.02 40.63,45.55 55.88,45.55 55.88,43.02 58.41,43.02 59.68,44.29 IC4.1 64.77,44.29 66.04,43.02 73.66,43.02 | 73.66,43.02 77.47,43.02 78.73,41.74 IC3.19 | IC3.11 77.47,21.43 77.47,36.66 76.2,37.94 73.66,37.94 73.66,43.02
N$6  (via drill 0.8 pad 1.27)
  Top 0.406: v60.95,55.72 59.68,56.98 59.68,59.52 58.41,60.8 58.41,61.43
  Top 1.27: 58.41,62.06 58.41,61.43 58.41,75.4
N$7  (via drill 0.8 pad 1.27)
  Bottom 0.406: v63.49,58.26 60.95,60.8 60.95,61.43
  Bottom 1.27: 60.95,62.06 60.95,61.43 60.95,75.4
N$8
  Bottom 0.406: IC5.12 58.41,23.96 59.68,22.7 62.22,22.7 62.22,23.96 63.49,25.23 69.84,25.23 71.12,23.96 IC3.9
N$9  (via drill 0.8)
  Top 0.406: IC3.14 81.28,29.05 81.28,36.66 82.55,36.66 82.55,48.09 v81.28,49.37 | v69.84,48.09 69.84,53.18 71.12,53.18 45-RAMDIS.1 72.39,56.98 72.39,59.52 71.12,60.8 71.12,61.43
  Top 1.27: 71.12,62.06 71.12,61.43 71.12,75.4
  Bottom 0.406: v81.28,49.37 81.28,48.09 v69.84,48.09
N$10
  Bottom 0.406: IC5.13 IC4.8
N$11
  Bottom 0.406: IC5.14 IC4.7
N$12
  Bottom 0.406: IC5.18 58.41,39.2 59.68,40.48 64.77,40.48 66.04,39.2 IC4.18
N$13
  Bottom 0.406: IC5.19 58.41,41.74 59.68,43.02 62.22,43.02 62.22,41.74 64.77,41.74 66.04,40.48 71.12,40.48 IC3.2
N$14  (via drill 0.8)
  Top 0.406: IC3.15 78.73,31.59 78.73,37.94 81.28,37.94 v81.28,46.83 | v67.31,49.37 67.31,51.91 43-ROMDIS.1 69.84,56.98 69.84,59.52 68.58,60.8 68.58,61.43
  Top 1.27: 68.58,62.06 68.58,61.43 68.58,75.4
  Bottom 0.406: v81.28,46.83 67.31,46.83 v67.31,49.37
N$15  (via drill 0.8 pad 1.27)
  Top 0.406: v63.49,55.72 62.22,56.98 62.22,59.52 60.95,60.8 60.95,61.43
  Top 1.27: 60.95,62.06 60.95,61.43 60.95,75.4
N$16  (via drill 0.8 pad 1.27)
  Top 0.406: v66.04,55.72 64.77,56.98 64.77,59.52 63.49,60.8 63.49,61.43
  Top 1.27: 63.49,62.06 63.49,61.43 63.49,75.4
N$17  (via drill 0.8 pad 1.27)
  Bottom 0.406: v68.58,58.26 66.04,60.8 66.04,61.43
  Bottom 1.27: 66.04,62.06 66.04,61.43 66.04,75.4
N$18  (via drill 0.8 pad 1.27)
  Bottom 0.406: v71.12,58.26 68.58,60.8 68.58,61.43
  Bottom 1.27: 68.58,62.06 68.58,61.43 68.58,75.4
N$19  (via drill 0.8 pad 1.27)
  Bottom 0.406: v73.66,58.26 71.12,60.8 71.12,61.43
  Bottom 1.27: 71.12,62.06 71.12,61.43 71.12,75.4
N$20  (via drill 0.8 pad 1.27)
  Bottom 0.406: v76.2,58.26 73.66,60.8 73.66,61.43
  Bottom 1.27: 73.66,62.06 73.66,61.43 73.66,75.4
N$21  (via drill 0.8 pad 1.27)
  Top 0.406: v76.2,55.72 74.93,56.98 74.93,59.52 73.66,60.8 73.66,61.43
  Top 1.27: 73.66,62.06 73.66,61.43 73.66,75.4
N$22  (via drill 0.8 pad 1.27)
  Top 0.406: SET.1 v11.42,58.26
  Bottom 0.406: v11.42,58.26 15.23,58.26 | 15.23,58.26 2-GND.1 | 15.23,58.26 15.23,61.43
  Bottom 1.27: 15.23,61.43 15.23,75.4
N$23  (via drill 0.8 pad 1.27)
  other vias: 35.55,46.83
N$27  (via drill 0.8 pad 1.27)
  Top 0.406: RN1.3 IC2.4 15.23,10 29.21,10 29.21,4.92 57.14,4.92 | v87.62,4.92 92.7,4.92 v92.7,16.35 | IC7.4 78.73,4.92 57.14,4.92 | 57.14,4.92 57.14,12.54 IC8.11
  Bottom 0.406: IC7.4 78.73,4.92 v87.62,4.92 | v92.7,16.35 92.7,18.89 95.25,18.89 95.25,39.2 IC6.6
N$28
  Top 0.406: RN1.6 IC2.7
  Bottom 0.406: RN1.6 22.86,1.1 91.44,1.1 91.44,17.62 86.36,17.62 | 86.36,17.62 IC7.10 | 86.36,17.62 82.55,17.62 81.28,18.89 74.93,18.89 74.93,20.16 71.12,20.16 71.12,18.89 68.58,18.89 68.58,16.35 IC8.9
N$29  (via drill 0.8 pad 1.27)
  Top 0.406: RN1.7 IC2.8 | IC8.3 53.34,12.54 54.6,13.81 v54.6,15.08
  Bottom 0.406: RN1.7 25.39,2.38 90.17,2.38 90.17,15.08 88.9,15.08 | 88.9,15.08 IC7.9 | 88.9,15.08 v54.6,15.08
N$30  (via drill 0.8 pad 1.27)
  Top 0.406: RN1.8 IC2.9 | v63.49,13.81 IC8.5 | IC7.7 v86.36,13.81
  Bottom 0.406: RN1.8 27.94,3.65 88.9,3.65 88.9,6.18 IC7.7 | v86.36,13.81 v63.49,13.81
N$31  (via drill 0.8 pad 1.27)
  Top 0.406: RN1.9 IC2.10 | IC8.7 63.49,6.18 68.58,6.18 v68.58,10
  Bottom 0.406: RN1.9 30.48,4.92 77.47,4.92 77.47,10 | 77.47,10 83.81,10 IC7.6 | 77.47,10 v68.58,10
N$32  (via drill 0.8 pad 1.27)
  Top 0.406: IC2.6 RN1.5 20.32,3.65 82.55,3.65 v82.55,12.54 | IC4.16 69.84,34.12 71.12,32.86 73.66,32.86 73.66,26.51 74.93,26.51 74.93,17.62 77.47,17.62 77.47,15.08 76.2,13.81 v76.2,12.54
  Bottom 0.406: v82.55,12.54 v76.2,12.54
N$33  (via drill 0.8 pad 1.27)
  Top 0.406: IC2.5 RN1.4 17.78,2.38 85.09,2.38 85.09,12.54 83.81,13.81 80.01,13.81 80.01,20.16 77.47,20.16 77.47,29.05 76.2,29.05 v76.2,31.59
  Bottom 0.406: IC4.17 69.84,36.66 69.84,34.12 71.12,32.86 74.93,32.86 74.93,31.59 v76.2,31.59
N$34
  Top 0.406: RN1.2 IC2.3 12.69,11.27 31.75,11.27 31.75,6.18 54.6,6.18 54.6,12.54 55.88,13.81 IC8.13
N$35  (via drill 0.8 pad 1.27)
  Top 0.406: IC8.1 48.25,11.27 50.79,13.81 IC8.15 v50.79,18.89 | v63.49,20.16 v63.49,22.7
  Bottom 0.406: v50.79,18.89 63.49,18.89 v63.49,20.16 | IC4.12 64.77,23.96 64.77,22.7 v63.49,22.7
N$37
  Bottom 0.406: Q1.B 85.09,23.96 82.55,23.96 | IC3.12 82.55,23.96 | 82.55,23.96 R2.2
N$38  (via drill 0.8 pad 1.27)
  Top 0.406: v86.36,6.18 91.44,6.18 91.44,17.62 90.17,18.89 90.17,26.51 92.7,26.51 92.7,32.86 | IC7.5 81.28,10 74.93,10 | 74.93,10 74.93,13.81 76.2,15.08 IC7.14 | 74.93,10 71.12,10 71.12,13.81 68.58,13.81 68.58,18.89 66.04,18.89 66.04,29.05 IC4.14 | 92.7,32.86 v91.44,32.86 | IC6.5 92.7,36.66 92.7,32.86
  Bottom 0.406: IC7.5 81.28,6.18 v86.36,6.18 | IC6.14 88.9,31.59 88.9,32.86 v91.44,32.86
N$39  (via drill 0.8 pad 1.27)
  Top 0.406: v83.81,18.89 IC7.11 | v90.17,27.78 90.17,35.4 91.44,35.4 v91.44,39.2
  Bottom 0.406: v91.44,39.2 IC6.11 | IC4.15 69.84,31.59 71.12,30.32 76.2,30.32 76.2,20.16 83.81,20.16 v83.81,18.89 88.9,18.89 88.9,27.78 v90.17,27.78
N$40  (via drill 0.8 pad 1.27)
  Top 0.406: IC7.12 81.28,15.08 90.17,15.08 90.17,17.62 88.9,18.89 88.9,36.66 v90.17,36.66 | IC4.13 69.84,26.51 71.12,25.23 73.66,25.23 v73.66,18.89
  Bottom 0.406: IC7.12 80.01,17.62 73.66,17.62 v73.66,18.89 | v90.17,36.66 IC6.12
N$42  (via drill 0.8 pad 1.27)
  Top 0.406: IC2.20 v27.94,39.2 | v63.49,43.02 62.22,43.02 62.22,45.55 60.95,45.55 v60.95,46.83 | v43.17,48.09 43.17,41.74 41.9,40.48 v41.9,39.2
  Bottom 0.406: v27.94,39.2 v41.9,39.2 | IC4.19 66.04,41.74 64.77,43.02 v63.49,43.02 | v60.95,46.83 60.95,48.09 v43.17,48.09
NMI  (via drill 0.8)
  Top 0.406: v78.73,49.37 78.73,39.2 IC3.18
  Bottom 0.406: v78.73,49.37 77.47,49.37 77.47,53.18 60.95,53.18 60.95,54.45 59.68,54.45 59.68,56.98 36-NMI.1 58.41,60.8 58.41,61.43
  Bottom 1.27: 58.41,62.06 58.41,61.43 58.41,75.4
RD  (via drill 0.8, 0.8 pad 1.27)
  Top 0.406: IC2.22 v22.86,39.2 | v46.98,39.2 46.98,45.55 48.25,45.55 49.52,46.83 49.52,50.63 v52.06,53.18 | v71.12,51.91 71.12,39.2 IC3.3
  Bottom 0.406: v22.86,39.2 24.12,37.94 30.48,37.94 30.48,36.66 44.45,36.66 45.71,37.94 45.71,39.2 v46.98,39.2 | v52.06,53.18 54.6,53.18 | 54.6,53.18 54.6,56.98 32-RD.1 53.34,60.8 53.34,61.43 | 54.6,53.18 59.68,53.18 59.68,51.91 v71.12,51.91
  Bottom 1.27: 53.34,62.06 53.34,61.43 53.34,75.4
RFSH  (via drill 0.8)
  Top 0.406: v63.49,39.2 63.49,37.94 58.41,37.94 v58.41,51.91
  Bottom 0.406: IC3.4 71.12,37.94 64.77,37.94 v63.49,39.2 | v58.41,51.91 50.79,51.91 50.79,54.45 52.06,54.45 52.06,56.98 30-RFSH.1 50.79,60.8 50.79,61.43
  Bottom 1.27: 50.79,62.06 50.79,61.43 50.79,75.4
VCC  (via drill 0.8 pad 1.27)
  Top 0.406: RN1.1 7.62,6.18 IC2.1 6.34,8.73 6.34,17.62 7.62,17.62 IC2.28 7.62,29.05 | 7.62,29.05 IC1.1 | IC1.28 5.08,44.29 5.08,29.05 7.62,29.05 | 45.71,16.35 IC8.16 | 45.71,16.35 44.45,16.35 44.45,40.48 45.71,41.74 v45.71,46.83 45.71,48.09 48.25,48.09 48.25,53.18 49.52,53.18 50.79,54.45 27-VCC.1 49.52,56.98 49.52,59.52 48.25,60.8 48.25,61.43 | v45.71,13.81 45.71,16.35 | IC6.16 85.09,26.51 85.09,40.48 88.9,40.48 v88.9,43.02 | IC7.16 71.12,20.16 67.31,20.16 67.31,27.78 69.84,27.78 69.84,32.86 67.31,32.86 67.31,44.29 IC4.20
  Top 1.27: 48.25,62.06 48.25,61.43 48.25,75.4
  Bottom 0.406: IC1.28 IC1.27 13.96,44.29 | IC2.1 7.62,13.81 v45.71,13.81 | IC6.16 Q1.C | 57.14,45.55 IC5.20 | 57.14,45.55 68.58,45.55 | 68.58,45.55 IC4.20 | 68.58,45.55 80.01,45.55 | 80.01,45.55 IC3.20 | 80.01,45.55 88.9,45.55 | 88.9,45.55 91.44,45.55 91.44,46.83 R1.2 | 88.9,45.55 v88.9,43.02 | 57.14,45.55 57.14,46.83 v45.71,46.83
WR  (via drill 0.8)
  Top 0.406: 55.88,61.43 55.88,60.8 57.14,59.52 57.14,56.98 33-WR.1 57.14,54.45 57.14,53.18 54.6,50.63 54.6,48.09 53.34,48.09 53.34,41.74 55.88,39.2 55.88,36.66 IC5.17 58.41,36.66 58.41,30.32 54.6,30.32 53.34,31.59 52.06,31.59 52.06,39.2 50.79,40.48 48.25,40.48 48.25,37.94 45.71,37.94 45.71,18.89 48.25,18.89 49.52,17.62 49.52,15.08 45.71,11.27 45.71,7.46 39.36,7.46 v39.36,11.27 | IC2.27 10.15,22.7 8.88,21.43 v8.88,16.35 | v20.32,12.54 16.51,16.35 v13.96,16.35
  Top 1.27: 55.88,62.06 55.88,61.43 55.88,75.4
  Bottom 0.406: v8.88,16.35 12.69,16.35 v13.96,16.35 | v39.36,11.27 38.09,12.54 v20.32,12.54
